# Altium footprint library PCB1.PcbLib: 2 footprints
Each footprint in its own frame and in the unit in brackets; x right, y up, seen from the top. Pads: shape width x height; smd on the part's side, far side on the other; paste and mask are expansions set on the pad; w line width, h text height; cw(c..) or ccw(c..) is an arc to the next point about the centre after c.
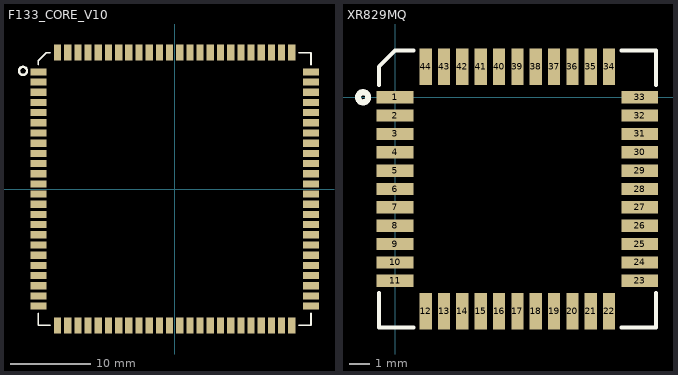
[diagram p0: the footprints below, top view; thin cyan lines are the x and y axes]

## F133_CORE_V10 [mm]
height 0.6
pads (96):
  rect 2x0.9 smd: 1(-17,14.605) 2(-17,13.335) 3(-17,12.065) 4(-17,10.795) 5(-17,9.525) 6(-17,8.255) 7(-17,6.985) 8(-17,5.715) 9(-17,4.445) 10(-17,3.175) 11(-17,1.905) 12(-17,0.635) 13(-17,-0.635) 14(-17,-1.905) 15(-17,-3.175) 16(-17,-4.445) 17(-17,-5.715) 18(-17,-6.985) 19(-17,-8.255) 20(-17,-9.525) 21(-17,-10.795) 22(-17,-12.065) 23(-17,-13.335) 24(-17,-14.605) 49(17,-14.605) 50(17,-13.335) 51(17,-12.065) 52(17,-10.795) 53(17,-9.525) 54(17,-8.255) 55(17,-6.985) 56(17,-5.715) 57(17,-4.445) 58(17,-3.175) 59(17,-1.905) 60(17,-0.635) 61(17,0.635) 62(17,1.905) 63(17,3.175) 64(17,4.445) 65(17,5.715) 66(17,6.985) 67(17,8.255) 68(17,9.525) 69(17,10.795) 70(17,12.065) 71(17,13.335) 72(17,14.605)
  rect 0.9x2 smd: 25(-14.605,-17) 26(-13.335,-17) 27(-12.065,-17) 28(-10.795,-17) 29(-9.525,-17) 30(-8.255,-17) 31(-6.985,-17) 32(-5.715,-17) 33(-4.445,-17) 34(-3.175,-17) 35(-1.905,-17) 36(-0.635,-17) 37(0.635,-17) 38(1.905,-17) 39(3.175,-17) 40(4.445,-17) 41(5.715,-17) 42(6.985,-17) 43(8.255,-17) 44(9.525,-17) 45(10.795,-17) 46(12.065,-17) 47(13.335,-17) 48(14.605,-17) 73(14.605,17) 74(13.335,17) 75(12.065,17) 76(10.795,17) 77(9.525,17) 78(8.255,17) 79(6.985,17) 80(5.715,17) 81(4.445,17) 82(3.175,17) 83(1.905,17) 84(0.635,17) 85(-0.635,17) 86(-1.905,17) 87(-3.175,17) 88(-4.445,17) 89(-5.715,17) 90(-6.985,17) 91(-8.255,17) 92(-9.525,17) 93(-10.795,17) 94(-12.065,17) 95(-13.335,17) 96(-14.605,17)
Top Overlay:
  circle w0.3: c-18.915,14.732 r0.5
  lines w0.2: -17,-15.5 -17,-17 -15.5,-17 ; -17,15.5 -17,16 -16,17 ; -16.9,16.1 -16,17 ; -15.5,17 -16,17 ; 15.5,-17 17,-17 17,-15.5 ; 15.5,17 17,17 17,15.5

## XR829MQ [mm]
pads (44):
  rect 1.8x0.6 smd: 1(0,0) 2(0,-0.9) 3(0,-1.8) 4(0,-2.7) 5(0,-3.6) 6(0,-4.5) 7(0,-5.4) 8(0,-6.3) 9(0,-7.2) 10(0,-8.1) 11(0,-9) 23(12,-9) 24(12,-8.1) 25(12,-7.2) 26(12,-6.3) 27(12,-5.4) 28(12,-4.5) 29(12,-3.6) 30(12,-2.7) 31(12,-1.8) 32(12,-0.9) 33(12,0)
  rect 0.6x1.8 smd: 12(1.5,-10.5) 13(2.4,-10.5) 14(3.3,-10.5) 15(4.2,-10.5) 16(5.1,-10.5) 17(6,-10.5) 18(6.9,-10.5) 19(7.8,-10.5) 20(8.7,-10.5) 21(9.6,-10.5) 22(10.5,-10.5) 34(10.5,1.5) 35(9.6,1.5) 36(8.7,1.5) 37(7.8,1.5) 38(6.9,1.5) 39(6,1.5) 40(5.1,1.5) 41(4.2,1.5) 42(3.3,1.5) 43(2.4,1.5) 44(1.5,1.5)
Top Overlay:
  circle w0.3: c-1.57,0 r0.25
  lines w0.2: -0.8,-9.6 -0.8,-11.3 0.9,-11.3 ; -0.8,0.6 -0.8,1.5 0,2.3 0.9,2.3 ; 11.1,-11.3 12.8,-11.3 12.8,-9.6 ; 11.1,2.3 12.8,2.3 12.8,0.6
